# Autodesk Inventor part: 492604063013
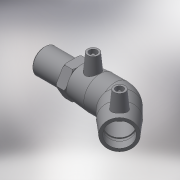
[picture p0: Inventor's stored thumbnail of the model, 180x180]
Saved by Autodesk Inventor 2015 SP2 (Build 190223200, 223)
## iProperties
Created: 2017-06
Part Number: 492604063013
Material: Generic
Description: PLASSON 45° ELBOW TRANSITION MALE 63-1.1/4"
Document SubType Name: Modeling
Designer: KIM
Mass: 476.6 g
Surface Area: 852.079 cm^2
Volume: 476.6 cm^3
Density: 1 g/cm^3
Appearance: Default
Author: KIM
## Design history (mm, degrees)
derived "492604.ipt"
feature "Solid1::492604.ipt"
tag "TaggingFeature1"
body "Solid1"
other parameters: "d2" = 82, "d4" = 37, "d5" = 73.8, "d8" = 168 deg, "d10" = 22.8, "d11" = 7.6, "d29" = 59, "d30" = 15, "d31" = 51.8, "d34" = 5 deg, "d41" = 4, "d42" = 14, "d43" = 0, "d49" = 63, "d50" = 40.95, "d51" = 22.8, "d52" = 58.71, "d54" = 135 deg, "d86" = 36.9, "d87" = 135 deg, "d88" = 148, "d90" = 57, "d91" = 0, "d92" = 57, "d93" = 0, "d101" = 3, "d102" = 0, "d107" = 0.1, "d108" = 48, "d109" = 41.91, "d110" = 36, "d111" = 9, "d112" = 82, "d113" = 29.337, "d114" = 32.4, "d116" = 2.46, "d122" = 0, "d123" = 2.0955, "d_" = 63, "L_" = 184, "L_1" = 57, "D_" = 48, "A_" = 59, "d_2" = 12, "L_2" = 36, "R_" = 41.91, "D_1" = 82
